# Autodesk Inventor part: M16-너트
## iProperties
IsCustomPart: 0
Company: 한국ATC센터
Created: 2009-02
Part Number: M16-너트
Material: Steel, Mild
Description: 플랜지붙이 6각 너트
Document SubType Name: Modeling
Standard: JIS B 1190
Designer: KYOUNG IL JANG
Standards Organization: JIS
Language: ko-KR
Size Designation: M 16
Categories: <MemberInstance><Categories><Category DisplayName="조임쇠" InternalName="e4da775c-781d-43d5-af7c-5136215cf5a6" Mnemonic="FSTN"><Category DisplayName="너트" InternalN
Density: 1 g/cm^3
Author: KYOUNG IL JANG
